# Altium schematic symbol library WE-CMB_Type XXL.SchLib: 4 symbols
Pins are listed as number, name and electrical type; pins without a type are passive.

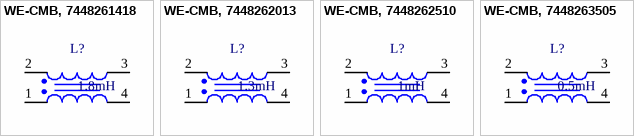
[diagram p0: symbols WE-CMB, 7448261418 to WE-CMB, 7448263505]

## WE-CMB, 7448261418
designator L?, comment 1.8mH
WE-CMB Common Mode Power Line Choke, Type XXL, 1.8mH; PartNumber: 7448261418
footprint WE-CMB_Type XXL_7448261418
pins: 1, 2, 3, 4

## WE-CMB, 7448262013
designator L?, comment 1.3mH
WE-CMB Common Mode Power Line Choke, Type XXL, 1.3mH; PartNumber: 7448262013
footprint WE-CMB_Type XXL_7448262013
pins: 1, 2, 3, 4

## WE-CMB, 7448262510
designator L?, comment 1mH
WE-CMB Common Mode Power Line Choke, Type XXL, 1mH; PartNumber: 7448262510
footprint WE-CMB_Type XXL_7448262510
pins: 1, 2, 3, 4

## WE-CMB, 7448263505
designator L?, comment 0.5mH
WE-CMB Common Mode Power Line Choke, Type XXL, 0.5mH; PartNumber: 7448263505
footprint WE-CMB_Type XXL_7448263505
pins: 1, 2, 3, 4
